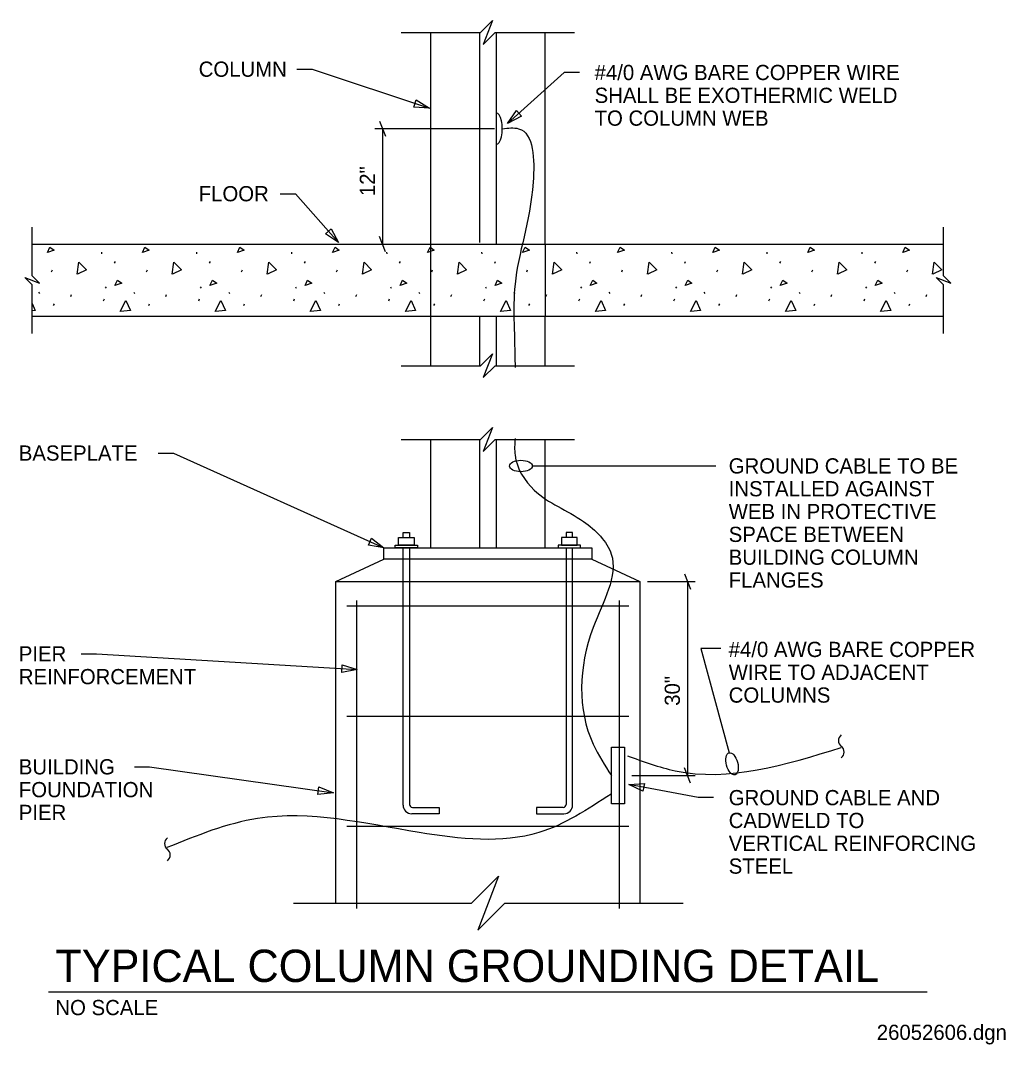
# Model space of a CAD drawing. Extents: x 10215.1 to 10258.3, y 10066.8 to 10111.7.
import ezdxf

# ---------------------------------------------------------------- set-up
doc = ezdxf.new("R2010")
doc.units = 0
for name, color, linetype in [('Level 3', 7, 'Continuous'), ('Level 50', 7, 'Continuous'), ('Level 51', 7, 'Continuous'), ('Level 52', 7, 'Continuous'), ('Level 60', 7, 'Continuous'), ('Level 61', 7, 'Continuous'), ('Level 62', 7, 'Continuous'), ('Level 63', 7, 'Continuous')]:
    doc.layers.add(name, color=color, linetype=linetype)

msp = doc.modelspace()

# ---------------------------------------------------------------- linework, layer by layer
at = {"layer": 'Level 50'}
for points in [[(10231.779, 10111.154), (10235.25, 10111.154), (10235.776, 10111.68), (10235.375, 10110.629), (10235.901, 10111.154), (10239.372, 10111.154)], [(10215.597, 10097.957), (10215.597, 10100.089), (10215.274, 10100.412), (10215.92, 10100.166), (10215.597, 10100.489), (10215.597, 10102.621)], [(10255.554, 10097.957), (10255.554, 10100.089), (10255.231, 10100.412), (10255.877, 10100.166), (10255.554, 10100.489), (10255.554, 10102.621)], [(10231.779, 10096.553), (10235.25, 10096.553), (10235.776, 10097.079), (10235.375, 10096.028), (10235.901, 10096.553), (10239.372, 10096.553)], [(10231.779, 10093.321), (10235.25, 10093.321), (10235.776, 10093.847), (10235.375, 10092.795), (10235.901, 10093.321), (10239.372, 10093.321)], [(10227.05, 10073.002), (10234.861, 10073.002), (10236.044, 10074.185), (10235.143, 10071.819), (10236.325, 10073.002), (10244.136, 10073.002)]]:
    msp.add_lwpolyline(points, dxfattribs=at)
at = {"layer": 'Level 51'}
for p, q in [((10227.21, 10109.546), (10227.877, 10109.546)), ((10227.877, 10109.546), (10233.017, 10107.831)), ((10238.923, 10109.401), (10236.443, 10107.16)), ((10239.59, 10109.401), (10238.923, 10109.401)), ((10226.475, 10104.089), (10227.142, 10104.089)), ((10227.142, 10104.089), (10229.026, 10101.946)), ((10221.125, 10092.724), (10221.792, 10092.724)), ((10221.792, 10092.724), (10231.015, 10088.567)), ((10245.568, 10092.156), (10237.526, 10092.156)), ((10244.197, 10087.427), (10244.464, 10086.761)), ((10242.577, 10087.094), (10244.664, 10087.094)), ((10244.331, 10087.094), (10244.331, 10078.592)), ((10217.75, 10083.927), (10218.416, 10083.927)), ((10218.416, 10083.927), (10229.844, 10083.233)), ((10220.08, 10078.975), (10220.747, 10078.975)), ((10220.747, 10078.975), (10228.803, 10077.839)), ((10244.464, 10078.258), (10244.197, 10078.925)), ((10241.894, 10078.592), (10244.664, 10078.592)), ((10244.803, 10077.625), (10241.753, 10078.198)), ((10245.469, 10077.625), (10244.803, 10077.625))]:
    msp.add_line(p, q, dxfattribs=at)
for points in [[(10232.438, 10108.2), (10233.017, 10107.831), (10232.332, 10107.884)], [(10237.05, 10107.483), (10236.443, 10107.16), (10236.826, 10107.731)], [(10228.711, 10102.557), (10229.026, 10101.946), (10228.461, 10102.337)], [(10230.476, 10088.993), (10231.015, 10088.567), (10230.339, 10088.689)], [(10229.189, 10083.44), (10229.844, 10083.233), (10229.169, 10083.107)], [(10228.166, 10078.097), (10228.803, 10077.839), (10228.119, 10077.767)], [(10242.377, 10077.911), (10241.753, 10078.198), (10242.439, 10078.238)]]:
    msp.add_lwpolyline(points, close=True, dxfattribs=at)
msp.add_lwpolyline([(10245.792, 10084.163), (10244.91, 10084.163), (10246.153, 10079.59)], dxfattribs=at)
for centre, major_axis in [((10237.026, 10092.156), (-0.5, 0)), ((10246.284, 10079.108), (0.131, -0.482))]:
    msp.add_ellipse(centre, major_axis=major_axis, ratio=0.5, dxfattribs=at)
at = {"layer": 'Level 52'}
msp.add_line((10216.313, 10069.113), (10254.838, 10069.113), dxfattribs=at)
at = {"layer": 'Level 60'}
for p, q in [((10235.213, 10111.154), (10235.213, 10101.95)), ((10235.938, 10111.154), (10235.938, 10101.898)), ((10235.213, 10098.701), (10235.213, 10096.553)), ((10235.938, 10098.701), (10235.938, 10096.553)), ((10235.213, 10093.321), (10235.213, 10088.567)), ((10235.938, 10093.321), (10235.938, 10088.567)), ((10229.819, 10086.264), (10229.819, 10072.762)), ((10241.332, 10086.264), (10241.332, 10072.762)), ((10229.396, 10086.023), (10241.754, 10086.023)), ((10229.396, 10081.201), (10241.754, 10081.201)), ((10229.396, 10076.379), (10241.754, 10076.379))]:
    msp.add_line(p, q, dxfattribs=at)
at = {"layer": 'Level 61'}
for p, q in [((10215.597, 10101.877), (10255.554, 10101.877)), ((10233.06, 10101.846), (10233.06, 10098.701)), ((10238.091, 10101.877), (10238.091, 10098.701)), ((10218.633, 10101.533), (10218.643, 10101.449)), ((10222.8, 10101.533), (10222.809, 10101.449)), ((10226.967, 10101.533), (10226.976, 10101.449)), ((10231.133, 10101.533), (10231.143, 10101.449)), ((10235.3, 10101.533), (10235.309, 10101.449)), ((10239.467, 10101.533), (10239.476, 10101.449)), ((10243.633, 10101.533), (10243.643, 10101.449)), ((10247.8, 10101.533), (10247.809, 10101.449)), ((10251.967, 10101.533), (10251.976, 10101.449)), ((10219.21, 10101.042), (10219.247, 10101.125)), ((10223.377, 10101.042), (10223.414, 10101.125)), ((10227.543, 10101.042), (10227.58, 10101.125)), ((10231.71, 10101.042), (10231.747, 10101.125)), ((10235.877, 10101.042), (10235.914, 10101.125)), ((10240.043, 10101.042), (10240.08, 10101.125)), ((10244.21, 10101.042), (10244.247, 10101.125)), ((10248.377, 10101.042), (10248.414, 10101.125)), ((10252.543, 10101.042), (10252.58, 10101.125)), ((10216.449, 10100.662), (10216.486, 10100.746)), ((10220.616, 10100.662), (10220.653, 10100.746)), ((10224.783, 10100.662), (10224.82, 10100.746)), ((10228.949, 10100.662), (10228.986, 10100.746)), ((10233.116, 10100.662), (10233.153, 10100.746)), ((10237.283, 10100.662), (10237.32, 10100.746)), ((10241.449, 10100.662), (10241.486, 10100.746)), ((10245.616, 10100.662), (10245.653, 10100.746)), ((10249.783, 10100.662), (10249.82, 10100.746)), ((10253.949, 10100.662), (10253.986, 10100.746)), ((10218.804, 10100.006), (10218.841, 10099.95)), ((10222.971, 10100.006), (10223.008, 10099.95)), ((10227.138, 10100.006), (10227.175, 10099.95)), ((10231.304, 10100.006), (10231.341, 10099.95)), ((10235.471, 10100.006), (10235.508, 10099.95)), ((10239.638, 10100.006), (10239.675, 10099.95)), ((10243.804, 10100.006), (10243.841, 10099.95)), ((10247.971, 10100.006), (10248.008, 10099.95)), ((10252.138, 10100.006), (10252.175, 10099.95)), ((10215.884, 10099.771), (10215.921, 10099.715)), ((10217.291, 10099.59), (10217.328, 10099.673)), ((10220.05, 10099.771), (10220.087, 10099.715)), ((10221.458, 10099.59), (10221.495, 10099.673)), ((10224.217, 10099.771), (10224.254, 10099.715)), ((10225.624, 10099.59), (10225.662, 10099.673)), ((10228.384, 10099.771), (10228.421, 10099.715)), ((10229.791, 10099.59), (10229.828, 10099.673)), ((10232.55, 10099.771), (10232.587, 10099.715)), ((10233.958, 10099.59), (10233.995, 10099.673)), ((10236.717, 10099.771), (10236.754, 10099.715)), ((10238.124, 10099.59), (10238.162, 10099.673)), ((10240.884, 10099.771), (10240.921, 10099.715)), ((10242.291, 10099.59), (10242.328, 10099.673)), ((10245.05, 10099.771), (10245.087, 10099.715)), ((10246.458, 10099.59), (10246.495, 10099.673)), ((10249.217, 10099.771), (10249.254, 10099.715)), ((10250.624, 10099.59), (10250.662, 10099.673)), ((10253.384, 10099.771), (10253.421, 10099.715)), ((10254.791, 10099.59), (10254.828, 10099.673)), ((10216.542, 10099.184), (10216.579, 10099.267)), ((10218.734, 10099.396), (10218.771, 10099.48)), ((10220.709, 10099.184), (10220.746, 10099.267)), ((10222.901, 10099.396), (10222.938, 10099.48)), ((10224.875, 10099.184), (10224.912, 10099.267)), ((10227.067, 10099.396), (10227.105, 10099.48)), ((10229.042, 10099.184), (10229.079, 10099.267)), ((10231.234, 10099.396), (10231.271, 10099.48)), ((10233.209, 10099.184), (10233.246, 10099.267)), ((10235.401, 10099.396), (10235.438, 10099.48)), ((10237.375, 10099.184), (10237.412, 10099.267)), ((10239.567, 10099.396), (10239.605, 10099.48)), ((10241.542, 10099.184), (10241.579, 10099.267)), ((10243.734, 10099.396), (10243.771, 10099.48)), ((10245.709, 10099.184), (10245.746, 10099.267)), ((10247.901, 10099.396), (10247.938, 10099.48)), ((10249.875, 10099.184), (10249.912, 10099.267)), ((10252.067, 10099.396), (10252.105, 10099.48)), ((10254.042, 10099.184), (10254.079, 10099.267)), ((10255.554, 10098.701), (10215.597, 10098.701)), ((10231.863, 10089.247), (10232.144, 10089.247)), ((10231.863, 10089.022), (10231.863, 10089.247)), ((10232.144, 10089.247), (10232.144, 10089.022)), ((10239.288, 10089.247), (10239.007, 10089.247)), ((10239.007, 10089.247), (10239.007, 10089.022)), ((10239.288, 10089.022), (10239.288, 10089.247)), ((10231.863, 10077.292), (10231.863, 10088.567)), ((10232.144, 10088.567), (10232.144, 10077.323)), ((10239.007, 10088.567), (10239.007, 10077.323)), ((10239.288, 10077.292), (10239.288, 10088.567)), ((10228.907, 10087.094), (10231.015, 10088.078)), ((10240.136, 10088.078), (10242.244, 10087.094)), ((10232.269, 10077.198), (10233.44, 10077.198)), ((10233.44, 10077.198), (10233.44, 10076.917)), ((10238.882, 10077.198), (10237.711, 10077.198)), ((10237.711, 10077.198), (10237.711, 10076.917)), ((10233.44, 10076.917), (10232.238, 10076.917)), ((10237.711, 10076.917), (10238.913, 10076.917))]:
    msp.add_line(p, q, dxfattribs=at)
for points in [[(10233.06, 10111.154), (10233.06, 10101.846)], [(10238.091, 10101.877), (10238.091, 10111.154)], [(10216.266, 10101.518), (10216.377, 10101.75), (10216.562, 10101.611), (10216.266, 10101.518)], [(10220.433, 10101.518), (10220.544, 10101.75), (10220.729, 10101.611), (10220.433, 10101.518)], [(10224.6, 10101.518), (10224.711, 10101.75), (10224.896, 10101.611), (10224.6, 10101.518)], [(10228.766, 10101.518), (10228.877, 10101.75), (10229.062, 10101.611), (10228.766, 10101.518)], [(10232.933, 10101.518), (10233.044, 10101.75), (10233.229, 10101.611), (10232.933, 10101.518)], [(10237.1, 10101.518), (10237.211, 10101.75), (10237.396, 10101.611), (10237.1, 10101.518)], [(10241.266, 10101.518), (10241.377, 10101.75), (10241.562, 10101.611), (10241.266, 10101.518)], [(10245.433, 10101.518), (10245.544, 10101.75), (10245.729, 10101.611), (10245.433, 10101.518)], [(10249.6, 10101.518), (10249.711, 10101.75), (10249.896, 10101.611), (10249.6, 10101.518)], [(10253.766, 10101.518), (10253.877, 10101.75), (10254.062, 10101.611), (10253.766, 10101.518)], [(10217.575, 10100.567), (10217.648, 10101.095), (10217.979, 10100.753), (10217.583, 10100.57)], [(10221.741, 10100.567), (10221.815, 10101.095), (10222.146, 10100.753), (10221.75, 10100.57)], [(10225.908, 10100.567), (10225.981, 10101.095), (10226.313, 10100.753), (10225.917, 10100.57)], [(10230.075, 10100.567), (10230.148, 10101.095), (10230.479, 10100.753), (10230.083, 10100.57)], [(10234.241, 10100.567), (10234.315, 10101.095), (10234.646, 10100.753), (10234.25, 10100.57)], [(10238.408, 10100.567), (10238.481, 10101.095), (10238.813, 10100.753), (10238.417, 10100.57)], [(10242.575, 10100.567), (10242.648, 10101.095), (10242.979, 10100.753), (10242.583, 10100.57)], [(10246.741, 10100.567), (10246.815, 10101.095), (10247.146, 10100.753), (10246.75, 10100.57)], [(10250.908, 10100.567), (10250.981, 10101.095), (10251.313, 10100.753), (10250.917, 10100.57)], [(10255.075, 10100.567), (10255.148, 10101.095), (10255.479, 10100.753), (10255.083, 10100.57)], [(10219.229, 10100.07), (10219.34, 10100.302), (10219.525, 10100.163), (10219.229, 10100.07)], [(10223.395, 10100.07), (10223.506, 10100.302), (10223.691, 10100.163), (10223.395, 10100.07)], [(10227.562, 10100.07), (10227.673, 10100.302), (10227.858, 10100.163), (10227.562, 10100.07)], [(10231.729, 10100.07), (10231.84, 10100.302), (10232.025, 10100.163), (10231.729, 10100.07)], [(10235.895, 10100.07), (10236.006, 10100.302), (10236.191, 10100.163), (10235.895, 10100.07)], [(10240.062, 10100.07), (10240.173, 10100.302), (10240.358, 10100.163), (10240.062, 10100.07)], [(10244.229, 10100.07), (10244.34, 10100.302), (10244.525, 10100.163), (10244.229, 10100.07)], [(10248.395, 10100.07), (10248.506, 10100.302), (10248.691, 10100.163), (10248.395, 10100.07)], [(10252.562, 10100.07), (10252.673, 10100.302), (10252.858, 10100.163), (10252.562, 10100.07)], [(10215.597, 10099.285), (10215.737, 10098.971), (10215.597, 10098.959)], [(10219.46, 10098.934), (10219.71, 10099.406), (10219.904, 10098.971), (10219.469, 10098.934)], [(10223.626, 10098.934), (10223.876, 10099.406), (10224.071, 10098.971), (10223.636, 10098.934)], [(10227.793, 10098.934), (10228.043, 10099.406), (10228.237, 10098.971), (10227.802, 10098.934)], [(10231.96, 10098.934), (10232.21, 10099.406), (10232.404, 10098.971), (10231.969, 10098.934)], [(10236.126, 10098.934), (10236.376, 10099.406), (10236.571, 10098.971), (10236.136, 10098.934)], [(10240.293, 10098.934), (10240.543, 10099.406), (10240.737, 10098.971), (10240.302, 10098.934)], [(10244.46, 10098.934), (10244.71, 10099.406), (10244.904, 10098.971), (10244.469, 10098.934)], [(10248.626, 10098.934), (10248.876, 10099.406), (10249.071, 10098.971), (10248.636, 10098.934)], [(10252.793, 10098.934), (10253.043, 10099.406), (10253.237, 10098.971), (10252.802, 10098.934)], [(10233.06, 10098.701), (10233.06, 10096.553)], [(10238.091, 10096.553), (10238.091, 10098.701)], [(10233.06, 10093.321), (10233.06, 10088.567), (10238.091, 10088.567), (10238.091, 10093.321)], [(10228.907, 10073.008), (10228.907, 10087.094), (10242.244, 10087.094), (10242.244, 10073.008)]]:
    msp.add_lwpolyline(points, dxfattribs=at)
for points in [[(10232.347, 10088.693), (10231.66, 10088.693), (10231.66, 10089.022), (10232.347, 10089.022)], [(10238.804, 10088.693), (10239.491, 10088.693), (10239.491, 10089.022), (10238.804, 10089.022)], [(10231.015, 10088.567), (10240.136, 10088.567), (10240.136, 10088.078), (10231.015, 10088.078)], [(10231.515, 10088.693), (10232.492, 10088.693), (10232.492, 10088.567), (10231.515, 10088.567)], [(10239.636, 10088.693), (10238.658, 10088.693), (10238.658, 10088.567), (10239.636, 10088.567)]]:
    msp.add_lwpolyline(points, close=True, dxfattribs=at)
for centre, radius, start, end in [((10232.238, 10077.292), 0.375, 180, 270), ((10232.269, 10077.323), 0.125, 180, 270), ((10238.882, 10077.323), 0.125, 270, 0), ((10238.913, 10077.292), 0.375, 270, 0)]:
    msp.add_arc(centre, radius, start, end, dxfattribs=at)
at = {"layer": 'Level 62'}
msp.add_lwpolyline([(10240.996, 10079.833), (10241.561, 10079.833), (10241.561, 10077.351), (10240.996, 10077.351)], close=True, dxfattribs=at)
for centre, start, end in [((10251.259, 10080.121), 126.8699, 233.1301), ((10250.884, 10079.621), 306.8699, 53.1301), ((10221.714, 10075.611), 126.8699, 233.1301), ((10221.339, 10075.111), 306.8699, 53.1301)]:
    msp.add_arc(centre, 0.313, start, end, dxfattribs=at)
msp.add_ellipse((10235.952, 10106.939), major_axis=(0, 0.687), ratio=0.372662, start_param=3.105896, end_param=6.318882, dxfattribs=at)
for points in [[(10236.209, 10106.939), (10236.926, 10106.939), (10237.559, 10104.602), (10236.768, 10100.118), (10236.768, 10096.583), (10236.768, 10096.477)], [(10236.768, 10093.365), (10236.768, 10092.626), (10237.612, 10091.096), (10239.774, 10089.724), (10240.986, 10088.3), (10240.196, 10085.082), (10240.196, 10079.964), (10240.996, 10078.592)], [(10241.692, 10079.463), (10243.782, 10078.8), (10251.071, 10079.82)], [(10240.978, 10077.78), (10237.818, 10076.097), (10232.568, 10076.097), (10225.482, 10076.709), (10221.506, 10075.434)]]:
    msp.add_spline(points, degree=3, dxfattribs=at)
at = {"layer": 'Level 63'}
for p, q in [((10230.829, 10107.273), (10231.095, 10106.606)), ((10235.875, 10106.939), (10230.629, 10106.939)), ((10230.962, 10106.939), (10230.962, 10101.877)), ((10231.095, 10101.544), (10230.829, 10102.21))]:
    msp.add_line(p, q, dxfattribs=at)

# ---------------------------------------------------------------- texts
at = {"layer": 'Level 3'}
for s, height, p in [('TYPICAL COLUMN GROUNDING DETAIL', 1.41667, (10216.619, 10069.545)), ('NO SCALE', 0.6667, (10216.619, 10068.092)), ('26052606.dgn', 0.66667, (10252.627, 10067.006))]:
    msp.add_text(s, height=height, dxfattribs=at).set_placement(p)
at = {"layer": 'Level 63'}
for s, height, p in [('COLUMN', 0.6667, (10222.901, 10109.213)), ('#4/0 AWG BARE COPPER WIRE', 0.66667, (10240.257, 10109.068)), ('SHALL BE EXOTHERMIC WELD', 0.66667, (10240.257, 10108.068)), ('TO COLUMN WEB', 0.66667, (10240.257, 10107.068)), ('FLOOR', 0.6667, (10222.901, 10103.756)), ('BASEPLATE', 0.6667, (10215.015, 10092.391)), ('GROUND CABLE TO BE', 0.66667, (10246.136, 10091.828)), ('INSTALLED AGAINST', 0.66667, (10246.136, 10090.828)), ('WEB IN PROTECTIVE', 0.66667, (10246.136, 10089.828)), ('SPACE BETWEEN', 0.66667, (10246.136, 10088.828)), ('BUILDING COLUMN', 0.66667, (10246.136, 10087.828)), ('FLANGES', 0.6667, (10246.136, 10086.828)), ('#4/0 AWG BARE COPPER', 0.66667, (10246.136, 10083.786)), ('PIER', 0.6667, (10215.015, 10083.594)), ('WIRE TO ADJACENT', 0.66667, (10246.136, 10082.786)), ('REINFORCEMENT', 0.66667, (10215.015, 10082.594)), ('COLUMNS', 0.6667, (10246.136, 10081.786)), ('BUILDING', 0.6667, (10215.015, 10078.642)), ('FOUNDATION', 0.6667, (10215.015, 10077.642)), ('GROUND CABLE AND', 0.66667, (10246.136, 10077.291)), ('PIER', 0.6667, (10215.015, 10076.642)), ('CADWELD TO', 0.6667, (10246.136, 10076.291)), ('VERTICAL REINFORCING', 0.66667, (10246.136, 10075.291)), ('STEEL', 0.6667, (10246.136, 10074.291))]:
    msp.add_text(s, height=height, dxfattribs=at).set_placement(p)
for s, p in [('12"', (10230.629, 10103.984)), ('30"', (10243.997, 10081.649))]:
    msp.add_text(s, height=0.6667, rotation=90, dxfattribs=at).set_placement(p)

doc.saveas('drawing.dxf')
